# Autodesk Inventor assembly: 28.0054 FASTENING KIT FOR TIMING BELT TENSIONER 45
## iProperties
Created: 2007-06
Part Number: 28.0054 FASTENING KIT FOR TIMING BELT TENSIONER 45
Document SubType Name: Assembly
Designer: Andy Moles
Author: Andy Moles
